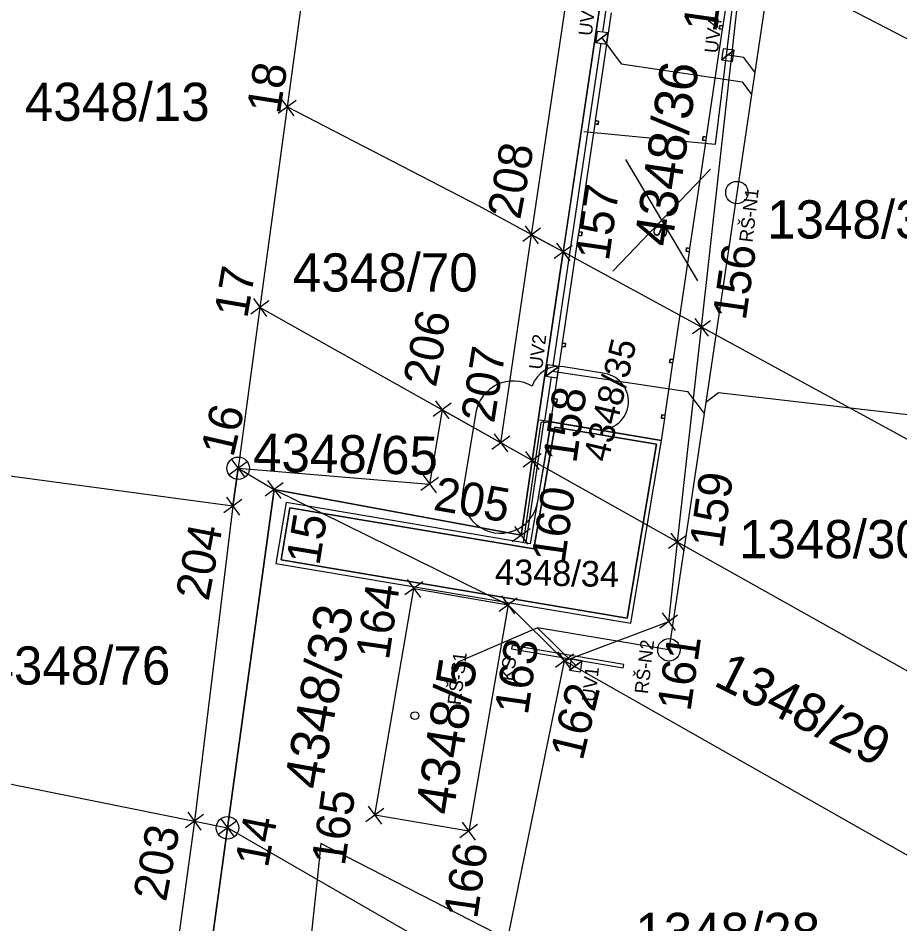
# Model space of a CAD drawing. Extents: x -735036 to -734743, y -1144813 to -1144181.
# Drawn here: x -734896.96 to -734857.76, y -1144568.07 to -1144527.79 of the extents above; entities that cross this region are included whole.
import ezdxf

# ---------------------------------------------------------------- set-up
doc = ezdxf.new("R2010")
doc.units = 0
for name, color, linetype in [('A3_BOURANÉ OBJEKTY', 7, 'Continuous'), ('A3_ODVODŇOVACÍ ŽLAB', 7, 'Continuous'), ('A3_SIT_OBJEKTY_N01', 7, 'Continuous'), ('A3_SIT_PNB', 7, 'Continuous'), ('BPEJ', 7, 'Continuous'), ('CKKOTY', 7, 'Continuous'), ('CKSTENY_SRAF', 7, 'Continuous'), ('CKTEXTY_MALE', 7, 'Continuous'), ('Groma (60)', 7, 'Continuous'), ('Katastr_HRANICE DRÁHY', 7, 'Continuous'), ('Katastr_Hranice parcel', 7, 'Continuous'), ('Katastr_Parcelní čísla', 7, 'Continuous'), ('Katastr_Značky kultur', 7, 'Continuous'), ('SO01_CKKANALIZACE_JEDNOTNA_PODZ_N', 7, 'Continuous'), ('SO05_CKKANALIZACE_JEDNOTNA_PODZ_N', 7, 'Continuous'), ('ZÁBORY_dočasné', 7, 'Continuous')]:
    doc.layers.add(name, color=color, linetype=linetype)

# ---------------------------------------------------------------- blocks, each defined once
blk = doc.blocks.new('POINT_DISPLAY')
for p, q in [((-0.35, -0.35), (0.35, 0.35)), ((-0.35, 0.35), (0.35, -0.35))]:
    blk.add_line(p, q)

msp = doc.modelspace()

# ---------------------------------------------------------------- linework, layer by layer
for p, q in [((-734871.293, -1144528.872), (-734870.725, -1144528.45)), ((-734865.695, -1144529.643), (-734865.127, -1144529.221)), ((-734873.494, -1144543.707), (-734872.926, -1144543.285)), ((-734872.456, -1144556.781), (-734871.88, -1144556.371))]:
    msp.add_line(p, q)
for points in [[(-734871.293, -1144528.872), (-734870.798, -1144528.945), (-734870.725, -1144528.45), (-734871.219, -1144528.377)], [(-734871.293, -1144528.872), (-734870.798, -1144528.945), (-734870.725, -1144528.45)], [(-734865.695, -1144529.643), (-734865.201, -1144529.716), (-734865.127, -1144529.221), (-734865.622, -1144529.148)], [(-734865.695, -1144529.643), (-734865.201, -1144529.716), (-734865.127, -1144529.221)], [(-734873.494, -1144543.707), (-734873, -1144543.78), (-734872.926, -1144543.285), (-734873.421, -1144543.212)], [(-734873.494, -1144543.707), (-734873, -1144543.78), (-734872.926, -1144543.285)], [(-734872.456, -1144556.781), (-734871.963, -1144556.864), (-734871.88, -1144556.371), (-734872.373, -1144556.288)], [(-734872.456, -1144556.781), (-734871.963, -1144556.864), (-734871.88, -1144556.371)]]:
    msp.add_lwpolyline(points, close=True)
at = {"layer": 'A3_BOURANÉ OBJEKTY'}
for p, q in [((-734866.751, -1144539.477), (-734869.95, -1144534.072)), ((-734866.175, -1144534.51), (-734870.526, -1144539.039))]:
    msp.add_line(p, q, dxfattribs=at)
msp.add_lwpolyline([(-734865.166, -1144526.906), (-734865.978, -1144533.409), (-734871.807, -1144532.846)], dxfattribs=at)
at = {"layer": 'A3_ODVODŇOVACÍ ŽLAB'}
for points in [[(-734870.972, -1144528.414), (-734867.824, -1144507.227), (-734866.588, -1144507.411)], [(-734873.174, -1144543.249), (-734871.046, -1144528.908)], [(-734874.496, -1144551.113), (-734873.702, -1144545.773), (-734873.54, -1144545.701), (-734873.249, -1144543.743)]]:
    msp.add_lwpolyline(points, dxfattribs=at)
at = {"layer": 'A3_SIT_OBJEKTY_N01'}
for p, q in [((-734873.262, -1144545.743), (-734874.2, -1144551.163)), ((-734874.036, -1144551.393), (-734873.099, -1144545.974)), ((-734868.356, -1144546.569), (-734873.262, -1144545.743)), ((-734873.099, -1144545.974), (-734868.587, -1144546.733)), ((-734868.587, -1144546.733), (-734869.889, -1144554.474)), ((-734869.725, -1144554.704), (-734868.356, -1144546.569)), ((-734885.047, -1144549.338), (-734885.503, -1144552.05)), ((-734885.273, -1144551.886), (-734884.883, -1144549.568)), ((-734874.2, -1144551.163), (-734885.047, -1144549.338)), ((-734884.883, -1144549.568), (-734874.036, -1144551.393)), ((-734885.503, -1144552.05), (-734869.725, -1144554.704)), ((-734869.889, -1144554.474), (-734885.273, -1144551.886)), ((-734875, -1144555.695), (-734875.026, -1144555.843)), ((-734870.032, -1144556.529), (-734875, -1144555.695)), ((-734875.026, -1144555.843), (-734870.057, -1144556.677)), ((-734870.057, -1144556.677), (-734870.032, -1144556.529))]:
    msp.add_line(p, q, dxfattribs=at)
for points in [[(-734888.44, -1144569.554), (-734887.65, -1144563.8), (-734885.58, -1144548.75), (-734874.6, -1144550.79), (-734868.084, -1144506.936)], [(-734870.591, -1144527.55), (-734871.304, -1144532.348), (-734871.156, -1144532.37), (-734871.178, -1144532.518), (-734871.326, -1144532.496), (-734872.039, -1144537.293), (-734871.89, -1144537.315), (-734871.912, -1144537.464), (-734872.061, -1144537.442), (-734872.774, -1144542.239), (-734872.625, -1144542.261), (-734872.647, -1144542.41), (-734872.796, -1144542.387), (-734873.141, -1144544.712), (-734872.993, -1144544.734), (-734873.015, -1144544.882), (-734873.163, -1144544.86), (-734873.293, -1144545.738), (-734868.362, -1144546.568), (-734868.217, -1144545.595), (-734868.366, -1144545.573), (-734868.344, -1144545.425), (-734868.195, -1144545.447), (-734867.85, -1144543.122), (-734867.998, -1144543.1), (-734867.976, -1144542.952), (-734867.828, -1144542.974), (-734867.115, -1144538.177), (-734867.263, -1144538.155), (-734867.241, -1144538.006), (-734867.093, -1144538.028), (-734866.38, -1144533.231), (-734866.529, -1144533.209), (-734866.507, -1144533.06), (-734866.358, -1144533.082), (-734865.645, -1144528.285), (-734865.794, -1144528.263), (-734865.772, -1144528.115), (-734865.623, -1144528.137), (-734864.911, -1144523.339)], [(-734865.623, -1144528.137), (-734865.772, -1144528.115), (-734865.794, -1144528.263), (-734865.645, -1144528.285), (-734865.623, -1144528.137)], [(-734871.156, -1144532.37), (-734871.304, -1144532.348), (-734871.326, -1144532.496), (-734871.178, -1144532.518), (-734871.156, -1144532.37)], [(-734866.358, -1144533.082), (-734866.507, -1144533.06), (-734866.529, -1144533.209), (-734866.38, -1144533.231), (-734866.358, -1144533.082)], [(-734871.89, -1144537.315), (-734872.039, -1144537.293), (-734872.061, -1144537.442), (-734871.912, -1144537.464), (-734871.89, -1144537.315)], [(-734867.093, -1144538.028), (-734867.241, -1144538.006), (-734867.263, -1144538.155), (-734867.115, -1144538.177), (-734867.093, -1144538.028)], [(-734872.625, -1144542.261), (-734872.774, -1144542.239), (-734872.796, -1144542.387), (-734872.647, -1144542.41), (-734872.625, -1144542.261)], [(-734867.828, -1144542.974), (-734867.976, -1144542.952), (-734867.998, -1144543.1), (-734867.85, -1144543.122), (-734867.828, -1144542.974)], [(-734873.163, -1144544.86), (-734873.015, -1144544.882), (-734872.993, -1144544.734), (-734873.141, -1144544.712), (-734873.163, -1144544.86)], [(-734868.195, -1144545.447), (-734868.344, -1144545.425), (-734868.366, -1144545.573), (-734868.217, -1144545.595), (-734868.195, -1144545.447)], [(-734873.262, -1144545.743), (-734873.293, -1144545.738), (-734873.603, -1144545.787), (-734874.397, -1144551.13)]]:
    msp.add_lwpolyline(points, dxfattribs=at)
for points in [[(-734869.725, -1144554.704), (-734868.356, -1144546.569), (-734873.262, -1144545.743), (-734874.2, -1144551.163), (-734885.047, -1144549.338), (-734885.503, -1144552.05)], [(-734869.889, -1144554.474), (-734868.587, -1144546.733), (-734873.099, -1144545.974), (-734874.036, -1144551.393), (-734884.883, -1144549.568), (-734885.273, -1144551.886)], [(-734875.026, -1144555.843), (-734870.057, -1144556.677), (-734870.032, -1144556.529), (-734875, -1144555.695)]]:
    msp.add_lwpolyline(points, close=True, dxfattribs=at)
at = {"layer": 'A3_SIT_PNB'}
for points in [[(-734870.874, -1144543.6), (-734872.698, -1144543.293)], [(-734876.611, -1144545.332), (-734877.183, -1144548.734)], [(-734873.86, -1144549.293), (-734873.287, -1144545.891), (-734873.262, -1144545.743), (-734873.114, -1144545.768), (-734871.29, -1144546.075)]]:
    msp.add_lwpolyline(points, dxfattribs=at)
for centre, radius, start, end in [((-734872.906, -1144544.531), 1.255, 80.4474, 162.539), ((-734871.082, -1144544.838), 1.255, 260.4493, 80.4493), ((-734874.949, -1144545.612), 1.685, 59.8843, 170.4485), ((-734875.521, -1144549.014), 1.685, 170.4493, 350.4493)]:
    msp.add_arc(centre, radius, start, end, dxfattribs=at)
at = {"layer": 'BPEJ'}
msp.add_lwpolyline([(-734830, -1144592), (-734842.48, -1144585.59), (-734843.64, -1144584.99), (-734844.95, -1144584.32), (-734858.71, -1144577.24), (-734875.19, -1144568.77), (-734883.5, -1144564.5), (-734883.67, -1144566.1), (-734885.13, -1144579.76), (-734886.01, -1144588.05), (-734886.05, -1144588.39), (-734886.47, -1144592.33), (-734886.95, -1144596.85), (-734888.29, -1144609.47)], dxfattribs=at)
at = {"layer": 'CKKOTY'}
msp.add_line((-734873.293, -1144545.738), (-734873.787, -1144545.665), dxfattribs=at)
at = {"layer": 'CKSTENY_SRAF'}
msp.add_line((-734885.58, -1144548.75), (-734886.194, -1144553.213), dxfattribs=at)
at = {"layer": 'CKTEXTY_MALE'}
for points in [[(-734873.87, -1144554.906), (-734877.406, -1144556.428)], [(-734877.406, -1144556.428), (-734877.429, -1144556.626)]]:
    msp.add_lwpolyline(points, dxfattribs=at)
at = {"layer": 'Katastr_HRANICE DRÁHY'}
for points in [[(-734882.78, -1144515.44), (-734885, -1144531.74)], [(-734885, -1144531.74), (-734886.21, -1144540.66)], [(-734886.21, -1144540.66), (-734887.18, -1144547.81)], [(-734887.18, -1144547.81), (-734885.58, -1144548.75)], [(-734885.58, -1144548.75), (-734887.65, -1144563.8)], [(-734887.65, -1144563.8), (-734889.5, -1144577.27)]]:
    msp.add_lwpolyline(points, dxfattribs=at)
at = {"layer": 'Katastr_Hranice parcel'}
for points in [[(-734870.33, -1144522.02), (-734872.73, -1144538.19)], [(-734866.58, -1144541.54), (-734864.73, -1144524.92)], [(-734864.73, -1144524.92), (-734851.62, -1144531.72)], [(-734876.5, -1144536.13), (-734885, -1144531.74)], [(-734872.73, -1144538.19), (-734876.5, -1144536.13)], [(-734872.73, -1144538.19), (-734874.11, -1144547.46)], [(-734866.58, -1144541.54), (-734872.73, -1144538.19)], [(-734874.11, -1144547.46), (-734886.21, -1144540.66)], [(-734867.65, -1144551.09), (-734866.58, -1144541.54)], [(-734852.48, -1144549.23), (-734866.58, -1144541.54)], [(-734874.11, -1144547.46), (-734874.6, -1144550.79)], [(-734867.65, -1144551.09), (-734874.11, -1144547.46)], [(-734887.41, -1144549.49), (-734900.43, -1144547.74)], [(-734887.18, -1144547.81), (-734887.41, -1144549.49)], [(-734874.6, -1144550.79), (-734885.58, -1144548.75)], [(-734885.58, -1144548.75), (-734875.18, -1144553.88)], [(-734868.04, -1144554.63), (-734867.65, -1144551.09)], [(-734853.62, -1144558.97), (-734867.65, -1144551.09)], [(-734881.1, -1144563.24), (-734879.37, -1144553.15)], [(-734879.37, -1144553.15), (-734875.18, -1144553.88)], [(-734875.18, -1144553.88), (-734876.93, -1144563.95)], [(-734875.18, -1144553.88), (-734872.67, -1144556.37)], [(-734872.67, -1144556.37), (-734868.04, -1144554.63)], [(-734875.6, -1144570.76), (-734872.67, -1144556.37)], [(-734854.52, -1144566.67), (-734872.67, -1144556.37)], [(-734902.26, -1144560.85), (-734887.65, -1144563.8)], [(-734876.93, -1144563.95), (-734881.1, -1144563.24)], [(-734875.6, -1144570.76), (-734887.65, -1144563.8)]]:
    msp.add_lwpolyline(points, dxfattribs=at)
at = {"layer": 'Katastr_Značky kultur'}
for p, q in [((-734887.23, -1144547.81), (-734887.13, -1144547.81)), ((-734887.7, -1144563.8), (-734887.6, -1144563.8))]:
    msp.add_line(p, q, dxfattribs=at)
for centre, radius in [((-734887.18, -1144547.81), 0.499), ((-734879.32, -1144558.81), 0.175), ((-734887.65, -1144563.8), 0.499)]:
    msp.add_circle(centre, radius, dxfattribs=at)
at = {"layer": 'SO01_CKKANALIZACE_JEDNOTNA_PODZ_N'}
msp.add_lwpolyline([(-734852.237, -1144546.036), (-734854.223, -1144545.804), (-734854.72, -1144545.746), (-734865.823, -1144544.448), (-734866.393, -1144544.885)], dxfattribs=at)
at = {"layer": 'SO05_CKKANALIZACE_JEDNOTNA_PODZ_N'}
msp.add_line((-734872.168, -1144556.576), (-734873.869, -1144554.902), dxfattribs=at)
for points in [[(-734866.341, -1144507.447), (-734861.751, -1144513.639), (-734864.21, -1144530.193), (-734864.357, -1144531.183), (-734866.393, -1144544.885), (-734866.467, -1144545.379), (-734868.027, -1144555.885), (-734873.869, -1144554.902)], [(-734871.009, -1144528.661), (-734870.152, -1144529.816), (-734864.775, -1144530.615), (-734864.357, -1144531.183)], [(-734864.21, -1144530.193), (-734864.695, -1144529.538), (-734865.411, -1144529.432)], [(-734873.21, -1144543.496), (-734867.201, -1144544.389), (-734866.467, -1144545.379)]]:
    msp.add_lwpolyline(points, dxfattribs=at)
for centre in [(-734865.006, -1144535.549), (-734868.027, -1144555.884)]:
    msp.add_circle(centre, 0.5, dxfattribs=at)
at = {"layer": 'ZÁBORY_dočasné'}
for p, q in [((-734874.131, -1144537.425), (-734871.733, -1144521.29)), ((-734870.326, -1144522.022), (-734872.73, -1144538.19)), ((-734875.505, -1144546.676), (-734874.131, -1144537.425)), ((-734872.73, -1144538.19), (-734874.131, -1144537.425)), ((-734874.106, -1144547.462), (-734872.73, -1144538.19)), ((-734878.111, -1144545.211), (-734878.665, -1144548.509)), ((-734874.106, -1144547.462), (-734878.111, -1144545.211)), ((-734874.6, -1144550.79), (-734874.106, -1144547.462)), ((-734887.41, -1144549.49), (-734887.18, -1144547.81)), ((-734887.18, -1144547.81), (-734885.58, -1144548.75)), ((-734887.18, -1144547.81), (-734878.665, -1144548.509)), ((-734885.58, -1144548.75), (-734887.65, -1144563.8)), ((-734885.58, -1144548.75), (-734874.6, -1144550.79)), ((-734887.41, -1144549.49), (-734889.125, -1144563.502)), ((-734889.125, -1144563.502), (-734890.986, -1144577.066)), ((-734887.65, -1144563.8), (-734889.5, -1144577.27)), ((-734889.125, -1144563.502), (-734887.65, -1144563.8))]:
    msp.add_line(p, q, dxfattribs=at)

# ---------------------------------------------------------------- block references
at = {"layer": 'Groma (60)', "rotation": -98.65482414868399}
for p in [(-734885, -1144531.74), (-734874.131, -1144537.425), (-734872.73, -1144538.19), (-734886.21, -1144540.66), (-734866.58, -1144541.54), (-734878.111, -1144545.211), (-734875.505, -1144546.676), (-734874.11, -1144547.46), (-734887.18, -1144547.81), (-734885.58, -1144548.75), (-734878.665, -1144548.509), (-734887.41, -1144549.49), (-734874.6, -1144550.79), (-734867.65, -1144551.09), (-734879.37, -1144553.15), (-734875.18, -1144553.88), (-734868.04, -1144554.63), (-734872.67, -1144556.37), (-734881.1, -1144563.24), (-734889.125, -1144563.502), (-734887.65, -1144563.8), (-734876.93, -1144563.95)]:
    msp.add_blockref('POINT_DISPLAY', p, dxfattribs=at)

# ---------------------------------------------------------------- texts
at = {"layer": 'CKTEXTY_MALE'}
for s, p in [('UV3', (-734871.455, -1144528.601)), ('UV4', (-734865.857, -1144529.372)), ('RŠ-N1', (-734864.312, -1144537.784)), ('S', (-734868.143, -1144537.587)), ('UV2', (-734873.659, -1144543.438)), ('RŠ-N2', (-734868.964, -1144557.864)), ('RŠ-S1', (-734877.284, -1144558.362)), ('KS', (-734874.936, -1144557.297)), ('UV1', (-734871.316, -1144558.219))]:
    msp.add_text(s, height=0.6, rotation=83.326, dxfattribs=at).set_placement(p)
at = {"layer": 'Groma (60)'}
for s, rotation, p in [('155', 81.7835, (-734865.933, -1144528.453)), ('18', 81.0515, (-734885.326, -1144532.098)), ('208', 79.2794, (-734874.646, -1144536.789)), ('157', 81.7835, (-734870.704, -1144538.624)), ('156', 81.7835, (-734864.616, -1144541.269)), ('17', 80.2712, (-734886.779, -1144541.181)), ('206', 78.4592, (-734878.393, -1144544.246)), ('207', 81.0053, (-734875.803, -1144545.841)), ('158', 81.7835, (-734872.152, -1144547.623)), ('16', 77.0228, (-734887.394, -1144547.359)), ('159', 81.7835, (-734865.64, -1144551.414)), ('205', 350.1624, (-734878.549, -1144549.65)), ('160', 81.7835, (-734872.668, -1144552.062)), ('15', 80.6206, (-734883.575, -1144552.171)), ('204', 79.207, (-734888.497, -1144553.753)), ('164', 81.7835, (-734880.479, -1144556.372)), ('163', 81.7835, (-734874.303, -1144558.82)), ('161', 81.7835, (-734867.074, -1144558.661)), ('162', 76.3695, (-734871.868, -1144560.857)), ('165', 81.7835, (-734882.441, -1144565.527)), ('14', 79.0027, (-734885.863, -1144565.62)), ('203', 79.207, (-734890.389, -1144567.128)), ('166', 81.7835, (-734876.556, -1144567.887))]:
    msp.add_text(s, height=1.5, rotation=rotation, dxfattribs=at).set_placement(p)
at = {"layer": 'Katastr_Parcelní čísla'}
for s, height, rotation, p in [('4348/36', 1.7, 81.4482, (-734867.908, -1144538.001)), ('4348/35', 1.14, 76.5179, (-734870.739, -1144547.577)), ('4348/65', 1.7, 358.9042, (-734886.526, -1144547.947)), ('4348/34', 1.14, 358.86, (-734875.77, -1144552.985)), ('4348/33', 1.7, 80.0265, (-734883.471, -1144562.144)), ('4348/5', 1.7, 80.9614, (-734877.631, -1144563.281)), ('1348/29', 1.7, 333.3928, (-734866.103, -1144557.435))]:
    msp.add_text(s, height=height, rotation=rotation, dxfattribs=at).set_placement(p)
for s, p in [('4348/13', (-734896.662, -1144532.363)), ('1348/31', (-734863.663, -1144537.59)), ('4348/70', (-734884.747, -1144539.95)), ('1348/30', (-734864.914, -1144551.81)), ('4348/76', (-734898.411, -1144557.43)), ('1348/28', (-734869.524, -1144569.28))]:
    msp.add_text(s, height=1.7, dxfattribs=at).set_placement(p)

doc.saveas('drawing.dxf')
